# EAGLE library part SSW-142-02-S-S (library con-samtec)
THROUGH-HOLE .025" SQ POST SOCKET Source: Samtec SSW.pdf
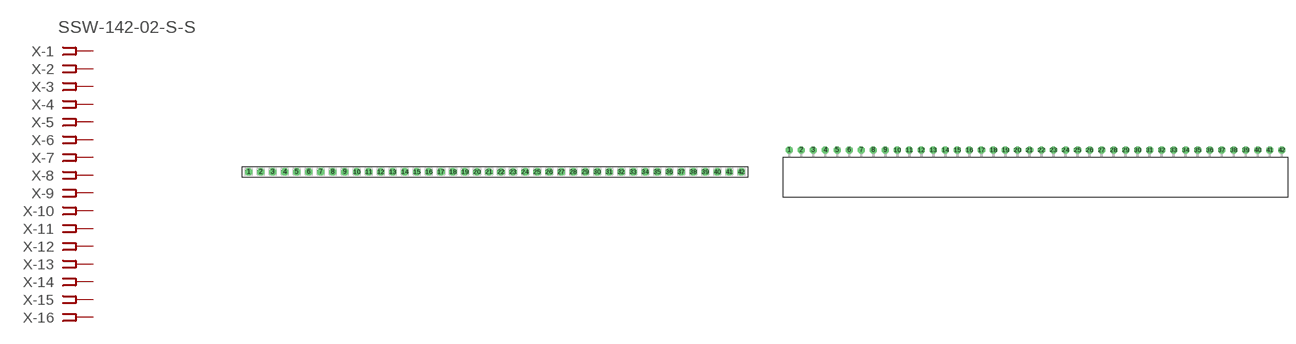
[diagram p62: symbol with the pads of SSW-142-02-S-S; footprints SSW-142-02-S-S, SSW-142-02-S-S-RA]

Designator prefix X; gates -1=FPINV -2=FPIN -3=FPIN -4=FPIN -5=FPIN -6=FPIN -7=FPIN -8=FPIN -9=FPIN -10=FPIN -11=FPIN -12=FPIN -13=FPIN -14=FPIN -15=FPIN -16=FPIN -17=FPIN -18=FPIN -19=FPIN -20=FPIN -21=FPIN -22=FPIN -23=FPIN -24=FPIN -25=FPIN -26=FPIN -27=FPIN -28=FPIN -29=FPIN -30=FPIN -31=FPIN -32=FPIN -33=FPIN -34=FPIN -35=FPIN -36=FPIN -37=FPIN -38=FPIN -39=FPIN -40=FPIN -41=FPIN -42=FPIN

## SSW-142-02-S-S (OC_FARNELL: unknown; OC_NEWARK: unknown)  [SSW-142-02-S-S]
1  -1:1  pas
2  -2:1  pas
3  -3:1  pas
4  -4:1  pas
5  -5:1  pas
6  -6:1  pas
7  -7:1  pas
8  -8:1  pas
9  -9:1  pas
10  -10:1  pas
11  -11:1  pas
12  -12:1  pas
13  -13:1  pas
14  -14:1  pas
15  -15:1  pas
16  -16:1  pas
17  -17:1  pas
18  -18:1  pas
19  -19:1  pas
20  -20:1  pas
21  -21:1  pas
22  -22:1  pas
23  -23:1  pas
24  -24:1  pas
25  -25:1  pas
26  -26:1  pas
27  -27:1  pas
28  -28:1  pas
29  -29:1  pas
30  -30:1  pas
31  -31:1  pas
32  -32:1  pas
33  -33:1  pas
34  -34:1  pas
35  -35:1  pas
36  -36:1  pas
37  -37:1  pas
38  -38:1  pas
39  -39:1  pas
40  -40:1  pas
41  -41:1  pas
42  -42:1  pas

## SSW-142-02-S-S-RA (OC_FARNELL: unknown; OC_NEWARK: unknown)  [SSW-142-02-S-S-RA]
Pads as for SSW-142-02-S-S

## Footprint SSW-142-02-S-S (pad centres in mm)
THROUGH-HOLE .025" SQ POST SOCKET Source: Samtec SSW.pdf
drill 1 pad 1.5 octagon: 1 -52.07,0; 2 -49.53,0; 3 -46.99,0; 4 -44.45,0; 5 -41.91,0; 6 -39.37,0; 7 -36.83,0; 8 -34.29,0; 9 -31.75,0; 10 -29.21,0; 11 -26.67,0; 12 -24.13,0; 13 -21.59,0; 14 -19.05,0; 15 -16.51,0; 16 -13.97,0; 17 -11.43,0; 18 -8.89,0; 19 -6.35,0; 20 -3.81,0; 21 -1.27,0; 22 1.27,0; 23 3.81,0; 24 6.35,0; 25 8.89,0; 26 11.43,0; 27 13.97,0; 28 16.51,0; 29 19.05,0; 30 21.59,0; 31 24.13,0; 32 26.67,0; 33 29.21,0; 34 31.75,0; 35 34.29,0; 36 36.83,0; 37 39.37,0; 38 41.91,0; 39 44.45,0; 40 46.99,0; 41 49.53,0; 42 52.07,0

## Footprint SSW-142-02-S-S-RA (pad centres in mm)
THROUGH-HOLE .025" SQ POST SOCKET Source: Samtec SSW.pdf
drill 1 pad 1.5 octagon: 1 -52.07,1.524; 2 -49.53,1.524; 3 -46.99,1.524; 4 -44.45,1.524; 5 -41.91,1.524; 6 -39.37,1.524; 7 -36.83,1.524; 8 -34.29,1.524; 9 -31.75,1.524; 10 -29.21,1.524; 11 -26.67,1.524; 12 -24.13,1.524; 13 -21.59,1.524; 14 -19.05,1.524; 15 -16.51,1.524; 16 -13.97,1.524; 17 -11.43,1.524; 18 -8.89,1.524; 19 -6.35,1.524; 20 -3.81,1.524; 21 -1.27,1.524; 22 1.27,1.524; 23 3.81,1.524; 24 6.35,1.524; 25 8.89,1.524; 26 11.43,1.524; 27 13.97,1.524; 28 16.51,1.524; 29 19.05,1.524; 30 21.59,1.524; 31 24.13,1.524; 32 26.67,1.524; 33 29.21,1.524; 34 31.75,1.524; 35 34.29,1.524; 36 36.83,1.524; 37 39.37,1.524; 38 41.91,1.524; 39 44.45,1.524; 40 46.99,1.524; 41 49.53,1.524; 42 52.07,1.524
